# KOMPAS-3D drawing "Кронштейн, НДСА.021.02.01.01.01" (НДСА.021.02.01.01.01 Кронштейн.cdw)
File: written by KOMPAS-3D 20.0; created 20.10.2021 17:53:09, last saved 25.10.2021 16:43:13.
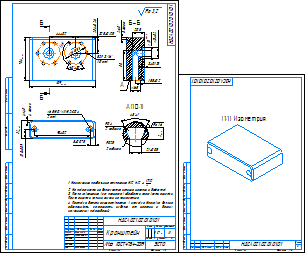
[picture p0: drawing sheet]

Sheet 1: A3, portrait
Sheet 2: A4, portrait

Document properties: Автор: adminzsc; Полное имя файла: C:\Users\vasilyeva\Desktop\PM_APPIUS\{67261e4b-eda1-4501-9485-e53a30bc741e}\НДСА.021.02.01.01.01 Кронштейн.cdw; PLM_CDWXDTO: <item xmlns="http://appius.ru/pdm" xmlns:xs="http://www.w3.org/2001/XMLSchema" xmlns:xsi="http://www.w3.org/2001/XMLSchema-instance" xsi:type="item">  <element xmlns:d2p1="http://v8.1c.ru/8.1/data/enterprise/current-config" xsi:type="d2p1:CatalogRef.aps_Элемен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; Масса: 0.56866; Параметр неуказанной шероховатости: Ra 3,2; PDM_DOCXDTO: <item xmlns="http://appius.ru/pdm" xmlns:xs="http://www.w3.org/2001/XMLSchema" xmlns:xsi="http://www.w3.org/2001/XMLSchema-instance" xsi:type="item">  <element xmlns:d2p1="http://v8.1c.ru/8.1/data/enterprise/current-config" xsi:type="d2p1:CatalogRef.aps_Элемен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; PDM_ITEMXDTO: <item xmlns="http://appius.ru/pdm" xmlns:xs="http://www.w3.org/2001/XMLSchema" xmlns:xsi="http://www.w3.org/2001/XMLSchema-instance" xsi:type="item">  <element xmlns:d2p1="http://v8.1c.ru/8.1/data/enterprise/current-config" xsi:type="d2p1:CatalogRef.aps_Элемен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; Форматы листов документа: A4, A3; PDM_DRAWINGXDTO: <item xmlns="http://appius.ru/pdm" xmlns:xs="http://www.w3.org/2001/XMLSchema" xmlns:xsi="http://www.w3.org/2001/XMLSchema-instance" xsi:type="item">  <element xmlns:d2p1="http://v8.1c.ru/8.1/data/enterprise/current-config" xsi:type="d2p1:CatalogRef.aps_Элемен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

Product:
- Part/product: Кронштейн  | designation НДСА.021.02.01.01.01
    Материал: АМг6  ГОСТ 4784-2019 (density 2640 kg/m3)
    Масса: 0.568658
    additional columns: <item xmlns="http://appius.ru/pdm" xmlns:xs="http://www.w3.org/2001/XMLSchema" x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; <item xmlns="http://appius.ru/pdm" xmlns:xs="http://www.w3.org/2001/XMLSchema" x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; <item xmlns="http://appius.ru/pdm" xmlns:xs="http://www.w3.org/2001/XMLSchema" x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
    source file: ..\НДСА.021.02.01.01.01 Кронштейн.cdw

Title block, sheet 1: Наименование: Кронштейн; designation: НДСА.021.02.01.01.01; Материал: АМг6  ГОСТ 4784-2019; Масса: 0,57 г; sheet number: 1; Количество листов документа: 2; organisation: ЭСТО; Форматы листов документа: A3; stored path: C:\Users\vasilyeva\Desktop\PM_APPIUS\НДСА.021.02.01.01.01 Кронштейн.cdw; Разработал: Васильева; Проверил: Горностаев; Утвердил: Белецкий; Разработал, date: 25.10.2021
Title block, sheet 2: Масса: 568,66 г; sheet number: 2; Форматы листов документа: A4

Views: Вид 1, Спереди, Проекционный вид 3, Вид 5, Изометрия, Разрез А-А, Выносной элемент 7, Разрез Б-Б, Выносной элемент А, Выносной элемент
Referenced files in C:\Users\vasilyeva\Desktop\PM_APPIUS\: НДСА.021.02.01.01.01 Кронштейн.m3d
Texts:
  JS12
  JS11
  BSF 3/16"
  Ra 1,6
  Ra 3,2
  НДСА.021.02.01.01.01 Кронштейн
Dimensions and other numbers on the sheet: 93±0,2; 15,5±0,09; 31; 2 отв; 8±0,075; 4; 4 фаски; 109; 38±0,08; 120; 10 отв.; 25,4±0,26; 32,5±0,125; 44±0,2; 70,4; 3±0,125; 18±0,2; 20,5; 10; 50; 16,5; 2; 8 фасок; 0,4; 2 радиуса; 0,25; 2,1±0,05; 1:1; 0,57 г; 1; 25.10.2021; 568,66 г

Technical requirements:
  Неуказанные предельные отклонения H12, h12,    IT12 2 .
  На поверхности не допускается наличие царапин и дефектов.
  После завершения всех процессов обработки произвести очистку.
  После очистки голыми руками не прикасаться.
  Поставка детали осуществляется в упаковке. Упаковка должна
  обеспечивать сохранность изделия от царапин и других
  механических повреждений.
